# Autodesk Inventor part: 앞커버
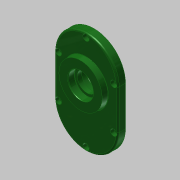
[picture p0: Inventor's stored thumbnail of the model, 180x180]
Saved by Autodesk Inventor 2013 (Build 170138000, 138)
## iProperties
Created: 2016-12
Part Number: 앞커버
Material: 일반
Document SubType Name: Modeling
Designer: mduedu
Density: 1 g/cm^3
Author: mduedu
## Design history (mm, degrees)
sketch "스케치1"
  geometry: L1 (40, -25)-(40, 25); L2 (-40, 25)-(-40, -25); L3 (-40, -25)-(40, 25); L4 (40, -25)-(-40, 25); A1 r 40 centre (0, 25) between (40, 25) and (-40, 25); A2 r 40 centre (0, -25) between (-40, -25) and (40, -25); 1 further point
  constraints: 8 end point, 4 point on circle, 4 tangent, 2 centre point, 2 midpoint, 1 parallel, 1 vertical
  dimensions: "d0" = 130 dimension on A2 A1; "d2" = 80 distance between parallel lines of L1 L2
extrude "돌출1" new body sketch "스케치1" distance "d3" = 10; taper "d4" = 0 deg
sketch "스케치2"
  geometry: C1 r 21 at (0, 11); 1 further point
  constraints: 1 centre point, 1 vertical alignment
  dimensions: "d5" = 42 diameter of C1; "d7" = 11 distance of C1.centre point (0, 0)
extrude "돌출2" join sketch "스케치2" distance "d8" = 7; taper "d9" = 0 deg
sketch "스케치3"
  geometry: C1 r 15 at (0, -33.1); C2 r 21 at (0, 11) reference; 1 further point
  constraints: 1 centre point, 1 vertical alignment
  dimensions: "d10" = 30 diameter of C1; "d71" = 44.1 distance of C1.centre C2.centre
extrude "돌출3" join sketch "스케치3" distance "d12" = 7; taper "d13" = 0 deg
sketch "스케치4"
  geometry: C1 r 28 at (0, 11); A1 r 21 centre (0, 11) between (8.978, -7.984) and (-8.978, -7.984) reference; 1 further point
  constraints: 1 centre point, 1 coincident
  dimensions: "d14" = 56 diameter of C1
extrude "돌출4" join sketch "스케치4" distance "d15" = 7; taper "d16" = -5 deg
hole "구멍1" diameter "d19" = 35; stored, may be unused: countersink angle "d23" = 90 deg, drill point angle "d25" = 0 deg; dims "d17" = 10, "d18" = 10, "d20" = 6, "d21" = 4, "d22" = 2, "d24" = 10
hole "구멍2" diameter "d28" = 22; stored, may be unused: countersink angle "d32" = 90 deg, drill point angle "d34" = 0 deg; dims "d26" = 10, "d27" = 10, "d29" = 6, "d30" = 4, "d31" = 2, "d33" = 7
hole "구멍3" diameter "d37" = 19; stored, may be unused: countersink angle "d41" = 90 deg, drill point angle "d43" = 0 deg; dims "d35" = 10, "d36" = 10, "d38" = 6, "d39" = 4, "d40" = 2, "d42" = 1
hole "구멍4" diameter "d46" = 32; stored, may be unused: countersink angle "d50" = 90 deg, drill point angle "d52" = 0 deg; dims "d47" = 6, "d48" = 4, "d49" = 2, "d51" = 8.3, "d89" = 10, "d90" = 10
hole "구멍5" diameter "d55" = 25; stored, may be unused: countersink angle "d59" = 90 deg, drill point angle "d61" = 0 deg; dims "d53" = 10, "d54" = 10, "d56" = 6, "d57" = 4, "d58" = 2, "d60" = 8
fillet "모깎기1" dims "d62" = 0.3
fillet "모깎기2" dims "d63" = 2
chamfer "모따기1" distance "d64" = 1; stored, may be unused: second distance "d65" = 2, angle "d66" = 45 deg
chamfer "모따기2" distance "d91" = 0.8; stored, may be unused: second distance "d92" = 2, angle "d93" = 30 deg
fillet "모깎기4" dims "d68" = 2
fillet "모깎기5" dims "d69" = 0.3
fillet "모깎기6" dims "d70" = 2
sketch "스케치5"
  geometry: L1 (-40, 25)-(-40, -25) reference; L2 (40, -25)-(40, 25) reference; L3 (35, 25)-(35, -25); L4 (-35, -25)-(-35, 25); A1 r 40 centre (0, 25) between (40, 25) and (-40, 25) reference; A2 r 40 centre (0, -25) between (-40, -25) and (40, -25) reference; A3 r 35 centre (0, 25) between (35, 25) and (-35, 25); A4 r 35 centre (0, -25) between (-35, -25) and (35, -25); 2 further points
  constraints: 5 point on circle, 4 end point, 2 centre point, 1 vertical alignment, 3 other
  dimensions: "d72" = 5 distance between parallel lines of L2 L3
sketch "스케치7"
  geometry: 1 further point
  constraints: 1 other
hole "구멍7" sketch "스케치7" at (0, 60) diameter "d80" = 4.5; stored, may be unused: countersink angle "d84" = 90 deg, drill point angle "d86" = 0 deg; dims "d81" = 6, "d82" = 8, "d83" = 4.6, "d85" = 8
node "솔리드1"
pattern_linear "직사각형 패턴1"
